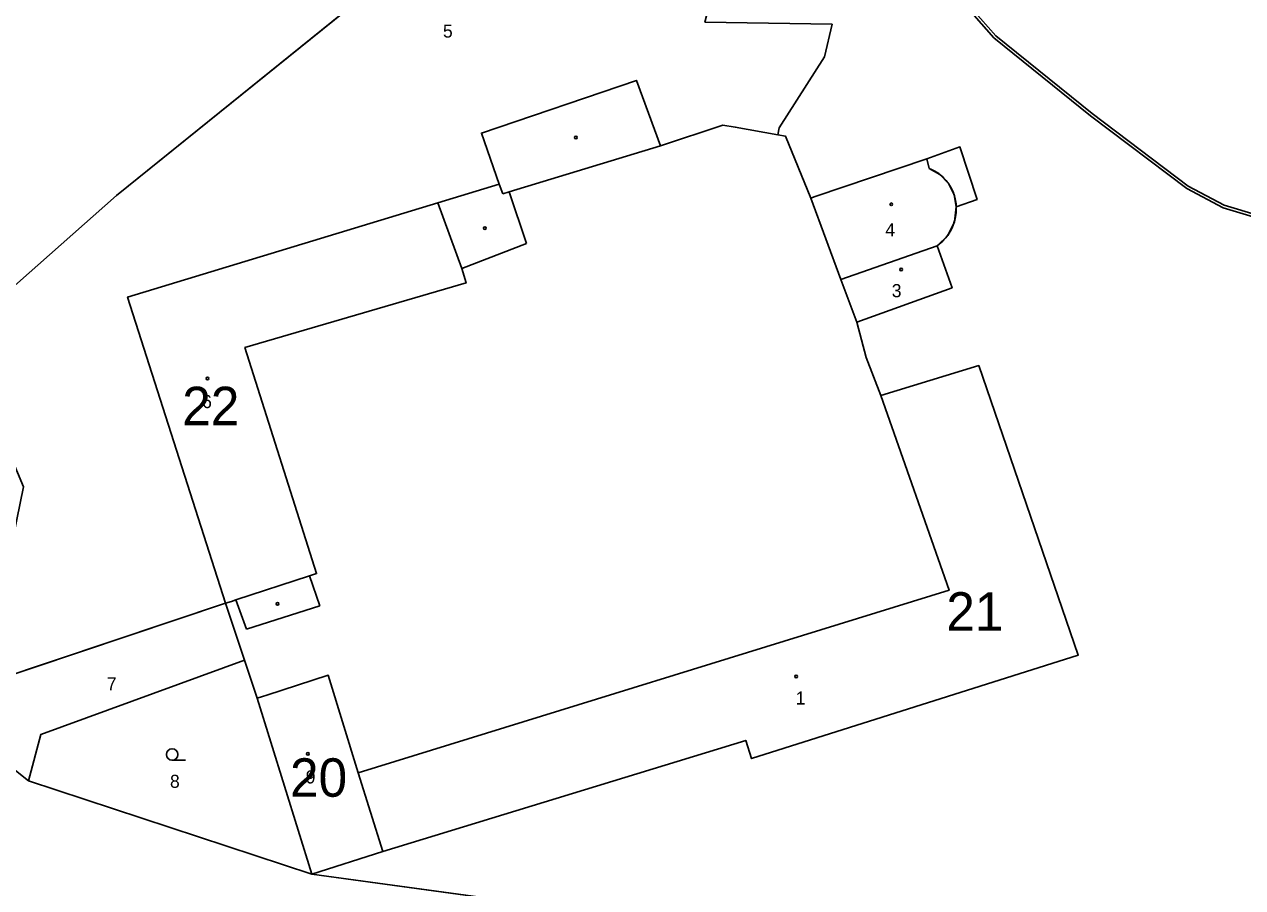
# Model space of a CAD drawing. Extents: x -689422 to -685210, y -987725 to -982160.
# Drawn here: x -686042.4 to -685883.9, y -987120.1 to -987007.8 of the extents above; entities that cross this region are included whole.
import ezdxf

# ---------------------------------------------------------------- set-up
doc = ezdxf.new("R2010")
doc.units = 0
for name, color, linetype in [('KN_Budovy', 7, 'Continuous'), ('KN_Budovy_cisla_domovni', 7, 'Continuous'), ('KN_Hranice_parcel', 7, 'Continuous'), ('KN_Hranice_parcel_vnitrni_kresba', 7, 'Continuous'), ('KN_Parcelni cisla', 7, 'Continuous'), ('KN_Polygon parcely', 7, 'Continuous'), ('KN_POZEMKY_ORNA PUDA', 7, 'Continuous'), ('KN_POZEMKY_OSTATNI PLOCHA', 7, 'Continuous'), ('KN_POZEMKY_TTP', 7, 'Continuous'), ('KN_POZEMKY_ZAHRADA', 7, 'Continuous'), ('KN_POZEMKY_ZASTAVENA PLOCHA', 7, 'Continuous'), ('KN_VYUZITI_16_ostatni plocha_silnice', 7, 'Continuous'), ('KN_VYUZITI_17_ostatni plocha_ostatni komunikace', 7, 'Continuous'), ('KN_VYUZITI_23_ostatni plocha_manipulacni plocha', 7, 'Continuous'), ('KN_Věcná břemena k části', 7, 'Continuous'), ('KN_Značky budov', 7, 'Continuous'), ('KN_Značky kultur', 7, 'Continuous')]:
    doc.layers.add(name, color=color, linetype=linetype)

msp = doc.modelspace()

# ---------------------------------------------------------------- linework, layer by layer
at = {"layer": 'KN_Budovy'}
for points in [[(-685939.49, -987030.22), (-685940.05, -987030.45), (-685936.15, -987041), (-685923.65, -987036.65), (-685922.26, -987035.27), (-685921.4, -987033.51), (-685921.15, -987031.56), (-685921.43, -987029.97), (-685922.16, -987028.54), (-685923.27, -987027.37), (-685924.67, -987026.57), (-685924.99, -987025.31)], [(-686028.95, -987043.29), (-686016.2, -987083.11), (-686015.44, -987082.86), (-686014.87, -987082.67), (-686005.31, -987079.54), (-686004.38, -987079.24), (-686013.69, -987049.87), (-685984.93, -987041.45), (-685985.48, -987039.58), (-685988.6, -987031.04)], [(-685934.1, -987046.54), (-685921.69, -987042.08), (-685923.65, -987036.65), (-685936.15, -987041)], [(-685998.97, -987105.14), (-685995.77, -987115.39), (-685948.53, -987100.93), (-685947.78, -987103.29), (-685905.27, -987089.86), (-685918.22, -987052.2), (-685930.96, -987056.09), (-685922.09, -987081.42)], [(-686012.08, -987095.43), (-686005, -987118.32), (-685995.77, -987115.39), (-685998.97, -987105.14), (-686002.86, -987092.46), (-686010.85, -987095.03), (-686011.42, -987095.22)]]:
    msp.add_lwpolyline(points, close=True, dxfattribs=at)
at = {"layer": 'KN_Hranice_parcel'}
for p, q in [((-685943.98, -986960.44), (-686030.41, -987030.08)), ((-686030.41, -987030.08), (-686044.81, -987042.84)), ((-685940.05, -987030.45), (-685936.15, -987041)), ((-685936.15, -987041), (-685923.65, -987036.65)), ((-685934.1, -987046.54), (-685936.15, -987041)), ((-686047.8, -987093.66), (-686016.2, -987083.11)), ((-686016.2, -987083.11), (-686013.73, -987090.49)), ((-686013.73, -987090.49), (-686012.08, -987095.43)), ((-686005, -987118.32), (-686012.08, -987095.43)), ((-686005, -987118.32), (-686041.83, -987106.17)), ((-685995.77, -987115.39), (-686005, -987118.32))]:
    msp.add_line(p, q, dxfattribs=at)
for points in [[(-685937.3, -987007.82), (-685938.29, -987012.04), (-685944.18, -987021.29), (-685944.36, -987022.19)], [(-685988.6, -987031.04), (-685980.6, -987028.61), (-685982.92, -987021.97), (-685962.77, -987015.13), (-685959.63, -987023.64), (-685951.53, -987020.94), (-685949.91, -987021.19), (-685944.36, -987022.19)], [(-685944.36, -987022.19), (-685943.35, -987022.38), (-685940.05, -987030.45)], [(-685924.99, -987025.31), (-685920.67, -987023.78), (-685918.44, -987030.6), (-685921.15, -987031.56)], [(-685940.05, -987030.45), (-685939.49, -987030.22), (-685924.99, -987025.31)], [(-686016.2, -987083.11), (-686028.95, -987043.29), (-685988.6, -987031.04)], [(-685988.6, -987031.04), (-685985.48, -987039.58), (-685984.93, -987041.45), (-686013.69, -987049.87), (-686004.38, -987079.24), (-686005.31, -987079.54), (-686014.87, -987082.67), (-686015.44, -987082.86), (-686016.2, -987083.11)], [(-685921.15, -987031.56), (-685921.17, -987032.33), (-685921.29, -987033.09), (-685921.51, -987033.83), (-685921.7, -987034.3), (-685922.07, -987034.98), (-685922.52, -987035.6), (-685923.05, -987036.16), (-685923.65, -987036.65)], [(-685923.65, -987036.65), (-685921.69, -987042.08), (-685934.1, -987046.54)], [(-685934.1, -987046.54), (-685932.88, -987051.14), (-685930.96, -987056.09), (-685918.22, -987052.2), (-685905.27, -987089.86), (-685947.78, -987103.29), (-685948.53, -987100.93), (-685995.77, -987115.39)], [(-686041.83, -987106.17), (-686052.84, -987097.52), (-686058.81, -987092.85), (-686061.49, -987085.48)], [(-686041.83, -987106.17), (-686040.25, -987100.18), (-686013.73, -987090.49)], [(-686012.08, -987095.43), (-686011.42, -987095.22), (-686010.85, -987095.03), (-686002.86, -987092.46), (-685998.97, -987105.14), (-685995.77, -987115.39)], [(-686005, -987118.32), (-685836.82, -987141.27), (-685828.14, -987142.95), (-685819.45, -987151.17)]]:
    msp.add_lwpolyline(points, dxfattribs=at)
at = {"layer": 'KN_Hranice_parcel_vnitrni_kresba'}
for p, q in [((-685979.31, -987029.61), (-685959.63, -987023.64)), ((-685924.99, -987025.31), (-685924.67, -987026.57)), ((-685980.6, -987028.61), (-685980.15, -987029.89)), ((-685980.15, -987029.89), (-685979.31, -987029.61)), ((-685979.31, -987029.61), (-685977.04, -987036.34)), ((-685985.48, -987039.58), (-685977.04, -987036.34)), ((-685930.96, -987056.09), (-685922.09, -987081.42)), ((-686005.31, -987079.54), (-686003.93, -987083.45)), ((-686014.87, -987082.67), (-686013.5, -987086.48)), ((-685998.97, -987105.14), (-685922.09, -987081.42)), ((-686013.5, -987086.48), (-686003.93, -987083.45))]:
    msp.add_line(p, q, dxfattribs=at)
msp.add_lwpolyline([(-685921.15, -987031.56), (-685921.16, -987031.35), (-685921.18, -987031.14), (-685921.2, -987030.94), (-685921.24, -987030.73), (-685921.28, -987030.53), (-685921.33, -987030.32), (-685921.38, -987030.12), (-685921.45, -987029.92), (-685921.52, -987029.73), (-685921.6, -987029.54), (-685921.69, -987029.34), (-685921.78, -987029.16), (-685921.88, -987028.97), (-685921.99, -987028.8), (-685922.1, -987028.62), (-685922.22, -987028.45), (-685922.35, -987028.29), (-685922.48, -987028.12), (-685922.62, -987027.97), (-685922.76, -987027.82), (-685922.91, -987027.67), (-685923.07, -987027.53), (-685923.23, -987027.4), (-685923.39, -987027.27), (-685923.57, -987027.15), (-685923.74, -987027.04), (-685923.92, -987026.93), (-685924.1, -987026.83), (-685924.29, -987026.74), (-685924.48, -987026.65), (-685924.67, -987026.57)], dxfattribs=at)
at = {"layer": 'KN_Polygon parcely'}
for points in [[(-686057.95, -987027.77), (-686044.81, -987042.84), (-686030.41, -987030.08), (-685943.98, -986960.44), (-685924.13, -986852.94), (-685913.21, -986806.14), (-685912.44, -986748.24), (-686007.7, -986854.28), (-685997.69, -986881.99), (-685975.19, -986944.25), (-685978.21, -986945.31), (-686044.53, -986968.62), (-686066.56, -986976.83), (-686064.65, -986989.12), (-686058.05, -987027.25)], [(-686016.2, -987083.11), (-686028.95, -987043.29), (-685988.6, -987031.04), (-685980.6, -987028.61), (-685982.92, -987021.97), (-685962.77, -987015.13), (-685959.63, -987023.64), (-685951.53, -987020.94), (-685949.91, -987021.19), (-685944.36, -987022.19), (-685944.18, -987021.29), (-685938.29, -987012.04), (-685937.3, -987007.82), (-685953.84, -987007.56), (-685941.2, -986958.77), (-685943.98, -986960.44), (-686030.41, -987030.08), (-686044.81, -987042.84), (-686051.22, -987045.66), (-686050.62, -987047.03), (-686049.49, -987051.75), (-686046.44, -987058.66), (-686042.51, -987067.97), (-686047.8, -987093.66)], [(-686013.73, -987090.49), (-686012.08, -987095.43), (-686011.42, -987095.22), (-686010.85, -987095.03), (-686002.86, -987092.46), (-685998.97, -987105.14), (-685995.77, -987115.39), (-685948.53, -987100.93), (-685947.78, -987103.29), (-685905.27, -987089.86), (-685918.22, -987052.2), (-685930.96, -987056.09), (-685932.88, -987051.14), (-685934.1, -987046.54), (-685936.15, -987041), (-685940.05, -987030.45), (-685943.35, -987022.38), (-685944.36, -987022.19), (-685949.91, -987021.19), (-685951.53, -987020.94), (-685959.63, -987023.64), (-685962.77, -987015.13), (-685982.92, -987021.97), (-685980.6, -987028.61), (-685988.6, -987031.04), (-685985.48, -987039.58), (-685984.93, -987041.45), (-686013.69, -987049.87), (-686004.38, -987079.24), (-686005.31, -987079.54), (-686014.87, -987082.67), (-686015.44, -987082.86), (-686016.2, -987083.11)], [(-685923.65, -987036.65), (-685923.05, -987036.16), (-685922.52, -987035.6), (-685922.07, -987034.98), (-685921.82, -987034.54), (-685921.51, -987033.83), (-685921.29, -987033.09), (-685921.17, -987032.33), (-685921.15, -987031.56), (-685918.44, -987030.6), (-685920.67, -987023.78), (-685924.99, -987025.31), (-685939.49, -987030.22), (-685940.05, -987030.45), (-685936.15, -987041)], [(-685988.6, -987031.04), (-686028.95, -987043.29), (-686016.2, -987083.11), (-686015.44, -987082.86), (-686014.87, -987082.67), (-686005.31, -987079.54), (-686004.38, -987079.24), (-686013.69, -987049.87), (-685984.93, -987041.45), (-685985.48, -987039.58)], [(-685934.1, -987046.54), (-685921.69, -987042.08), (-685923.65, -987036.65), (-685936.15, -987041)], [(-686013.73, -987090.49), (-686016.2, -987083.11), (-686047.8, -987093.66), (-686049.2, -987094.6), (-686052.96, -987093.52), (-686055.58, -987091.86), (-686059.81, -987087.86), (-686061.49, -987085.48), (-686058.81, -987092.85), (-686052.84, -987097.52), (-686041.83, -987106.17), (-686040.25, -987100.18)], [(-686005, -987118.32), (-686012.08, -987095.43), (-686013.73, -987090.49), (-686040.25, -987100.18), (-686041.83, -987106.17)], [(-685995.77, -987115.39), (-685998.97, -987105.14), (-686002.86, -987092.46), (-686010.85, -987095.03), (-686011.42, -987095.22), (-686012.08, -987095.43), (-686005, -987118.32)]]:
    msp.add_lwpolyline(points, close=True, dxfattribs=at)
for points in [[(-685836.82, -987141.27), (-686005, -987118.32), (-686041.83, -987106.17), (-686052.84, -987097.52), (-686058.81, -987092.85), (-686061.49, -987085.48), (-686064.52, -987080.49), (-686065.84, -987078.1), (-686071.7, -987067.5), (-686075.47, -987059.13), (-686075.94, -987058.09), (-686080.66, -987046.34), (-686084.5, -987036.79), (-686086.08, -987032.29), (-686090.96, -987018.42), (-686097.69, -986999.31)], [(-685937.3, -987007.82), (-685938.29, -987012.04), (-685944.18, -987021.29), (-685944.36, -987022.19), (-685943.35, -987022.38), (-685940.05, -987030.45), (-685939.49, -987030.22), (-685924.99, -987025.31), (-685920.67, -987023.78), (-685918.44, -987030.6), (-685921.15, -987031.56), (-685921.17, -987032.33), (-685921.29, -987033.09), (-685921.51, -987033.83), (-685921.7, -987034.3), (-685922.07, -987034.98), (-685922.52, -987035.6), (-685923.05, -987036.16), (-685923.65, -987036.65), (-685921.69, -987042.08), (-685934.1, -987046.54), (-685932.88, -987051.14), (-685930.96, -987056.09), (-685918.22, -987052.2), (-685905.27, -987089.86), (-685947.78, -987103.29), (-685948.53, -987100.93), (-685995.77, -987115.39), (-686005, -987118.32), (-685836.82, -987141.27)]]:
    msp.add_lwpolyline(points, dxfattribs=at)
at = {"layer": 'KN_POZEMKY_ORNA PUDA'}
for p, q in [((-685943.98, -986960.44), (-686030.41, -987030.08)), ((-686030.41, -987030.08), (-686044.81, -987042.84))]:
    msp.add_line(p, q, dxfattribs=at)
at = {"layer": 'KN_POZEMKY_OSTATNI PLOCHA'}
for p, q in [((-686030.41, -987030.08), (-685943.98, -986960.44)), ((-685937.3, -987007.82), (-685938.29, -987012.04)), ((-685938.29, -987012.04), (-685944.18, -987021.29)), ((-685962.77, -987015.13), (-685982.92, -987021.97)), ((-685959.63, -987023.64), (-685962.77, -987015.13)), ((-685951.53, -987020.94), (-685959.63, -987023.64)), ((-685949.91, -987021.19), (-685951.53, -987020.94)), ((-685982.92, -987021.97), (-685980.6, -987028.61)), ((-685944.36, -987022.19), (-685949.91, -987021.19)), ((-685944.18, -987021.29), (-685944.36, -987022.19)), ((-685980.6, -987028.61), (-685988.6, -987031.04)), ((-686044.81, -987042.84), (-686030.41, -987030.08)), ((-685988.6, -987031.04), (-686028.95, -987043.29)), ((-686028.95, -987043.29), (-686016.2, -987083.11)), ((-686016.2, -987083.11), (-686047.8, -987093.66)), ((-686047.8, -987093.66), (-686016.2, -987083.11)), ((-686016.2, -987083.11), (-686013.73, -987090.49)), ((-686013.73, -987090.49), (-686040.25, -987100.18)), ((-686041.83, -987106.17), (-686052.84, -987097.52)), ((-686052.84, -987097.52), (-686041.83, -987106.17)), ((-686040.25, -987100.18), (-686041.83, -987106.17)), ((-686041.83, -987106.17), (-686005, -987118.32)), ((-686005, -987118.32), (-685836.82, -987141.27))]:
    msp.add_line(p, q, dxfattribs=at)
at = {"layer": 'KN_POZEMKY_TTP'}
for p, q in [((-685938.29, -987012.04), (-685937.3, -987007.82)), ((-685944.18, -987021.29), (-685938.29, -987012.04)), ((-685944.36, -987022.19), (-685944.18, -987021.29)), ((-685943.35, -987022.38), (-685944.36, -987022.19)), ((-685940.05, -987030.45), (-685943.35, -987022.38)), ((-685920.67, -987023.78), (-685924.99, -987025.31)), ((-685918.44, -987030.6), (-685920.67, -987023.78)), ((-685924.99, -987025.31), (-685939.49, -987030.22)), ((-685939.49, -987030.22), (-685940.05, -987030.45)), ((-685921.19, -987032.54), (-685921.15, -987031.56)), ((-685921.15, -987031.56), (-685918.44, -987030.6)), ((-685921.15, -987031.56), (-685921.15, -987031.56)), ((-685921.76, -987034.42), (-685921.4, -987033.51)), ((-685921.4, -987033.51), (-685921.19, -987032.54)), ((-685922.9, -987036.02), (-685922.26, -987035.27)), ((-685922.26, -987035.27), (-685921.76, -987034.42)), ((-685923.65, -987036.65), (-685922.9, -987036.02)), ((-685921.69, -987042.08), (-685923.65, -987036.65)), ((-685934.1, -987046.54), (-685921.69, -987042.08)), ((-685932.88, -987051.14), (-685934.1, -987046.54)), ((-685930.96, -987056.09), (-685932.88, -987051.14)), ((-685918.22, -987052.2), (-685930.96, -987056.09)), ((-685905.27, -987089.86), (-685918.22, -987052.2)), ((-685947.78, -987103.29), (-685905.27, -987089.86)), ((-685995.77, -987115.39), (-685948.53, -987100.93)), ((-685948.53, -987100.93), (-685947.78, -987103.29)), ((-686005, -987118.32), (-685995.77, -987115.39)), ((-685836.82, -987141.27), (-686005, -987118.32))]:
    msp.add_line(p, q, dxfattribs=at)
at = {"layer": 'KN_POZEMKY_ZAHRADA'}
for p, q in [((-686040.25, -987100.18), (-686013.73, -987090.49)), ((-686013.73, -987090.49), (-686012.08, -987095.43)), ((-686012.08, -987095.43), (-686005, -987118.32)), ((-686041.83, -987106.17), (-686040.25, -987100.18)), ((-686005, -987118.32), (-686041.83, -987106.17))]:
    msp.add_line(p, q, dxfattribs=at)
at = {"layer": 'KN_POZEMKY_ZASTAVENA PLOCHA'}
for p, q in [((-685982.92, -987021.97), (-685962.77, -987015.13)), ((-685962.77, -987015.13), (-685959.63, -987023.64)), ((-685959.63, -987023.64), (-685951.53, -987020.94)), ((-685951.53, -987020.94), (-685949.91, -987021.19)), ((-685980.6, -987028.61), (-685982.92, -987021.97)), ((-685949.91, -987021.19), (-685944.36, -987022.19)), ((-685944.36, -987022.19), (-685943.35, -987022.38)), ((-685943.35, -987022.38), (-685940.05, -987030.45)), ((-685924.99, -987025.31), (-685920.67, -987023.78)), ((-685920.67, -987023.78), (-685918.44, -987030.6)), ((-685939.49, -987030.22), (-685924.99, -987025.31)), ((-685988.6, -987031.04), (-685980.6, -987028.61)), ((-685940.05, -987030.45), (-685939.49, -987030.22)), ((-685940.05, -987030.45), (-685936.15, -987041)), ((-685936.15, -987041), (-685940.05, -987030.45)), ((-686028.95, -987043.29), (-685988.6, -987031.04)), ((-685985.48, -987039.58), (-685988.6, -987031.04)), ((-685988.6, -987031.04), (-685985.48, -987039.58)), ((-685921.15, -987031.56), (-685921.19, -987032.54)), ((-685918.44, -987030.6), (-685921.15, -987031.56)), ((-685921.4, -987033.51), (-685921.76, -987034.42)), ((-685921.19, -987032.54), (-685921.4, -987033.51)), ((-685922.26, -987035.27), (-685922.9, -987036.02)), ((-685921.76, -987034.42), (-685922.26, -987035.27)), ((-685923.65, -987036.65), (-685936.15, -987041)), ((-685936.15, -987041), (-685923.65, -987036.65)), ((-685922.9, -987036.02), (-685923.65, -987036.65)), ((-685923.65, -987036.65), (-685923.65, -987036.65)), ((-685923.65, -987036.65), (-685921.69, -987042.08)), ((-685984.93, -987041.45), (-685985.48, -987039.58)), ((-685985.48, -987039.58), (-685984.93, -987041.45)), ((-686013.69, -987049.87), (-685984.93, -987041.45)), ((-685984.93, -987041.45), (-686013.69, -987049.87)), ((-685936.15, -987041), (-685934.1, -987046.54)), ((-685934.1, -987046.54), (-685936.15, -987041)), ((-685921.69, -987042.08), (-685934.1, -987046.54)), ((-686016.2, -987083.11), (-686028.95, -987043.29)), ((-685934.1, -987046.54), (-685932.88, -987051.14)), ((-686004.38, -987079.24), (-686013.69, -987049.87)), ((-686013.69, -987049.87), (-686004.38, -987079.24)), ((-685932.88, -987051.14), (-685930.96, -987056.09)), ((-685930.96, -987056.09), (-685918.22, -987052.2)), ((-685918.22, -987052.2), (-685905.27, -987089.86)), ((-686014.87, -987082.67), (-686005.31, -987079.54)), ((-686005.31, -987079.54), (-686014.87, -987082.67)), ((-686005.31, -987079.54), (-686004.38, -987079.24)), ((-686004.38, -987079.24), (-686005.31, -987079.54)), ((-686016.2, -987083.11), (-686015.44, -987082.86)), ((-686015.44, -987082.86), (-686016.2, -987083.11)), ((-686015.44, -987082.86), (-686014.87, -987082.67)), ((-686014.87, -987082.67), (-686015.44, -987082.86)), ((-686013.73, -987090.49), (-686016.2, -987083.11)), ((-686012.08, -987095.43), (-686013.73, -987090.49)), ((-685905.27, -987089.86), (-685947.78, -987103.29)), ((-686010.85, -987095.03), (-686002.86, -987092.46)), ((-686002.86, -987092.46), (-686010.85, -987095.03)), ((-686002.86, -987092.46), (-685998.97, -987105.14)), ((-685998.97, -987105.14), (-686002.86, -987092.46)), ((-686012.08, -987095.43), (-686011.42, -987095.22)), ((-686011.42, -987095.22), (-686012.08, -987095.43)), ((-686005, -987118.32), (-686012.08, -987095.43)), ((-686011.42, -987095.22), (-686010.85, -987095.03)), ((-686010.85, -987095.03), (-686011.42, -987095.22)), ((-685948.53, -987100.93), (-685995.77, -987115.39)), ((-685947.78, -987103.29), (-685948.53, -987100.93)), ((-685998.97, -987105.14), (-685995.77, -987115.39)), ((-685995.77, -987115.39), (-685998.97, -987105.14)), ((-685995.77, -987115.39), (-686005, -987118.32))]:
    msp.add_line(p, q, dxfattribs=at)
at = {"layer": 'KN_VYUZITI_16_ostatni plocha_silnice'}
for p, q in [((-686052.84, -987097.52), (-686041.83, -987106.17)), ((-686041.83, -987106.17), (-686005, -987118.32)), ((-686005, -987118.32), (-685836.82, -987141.27))]:
    msp.add_line(p, q, dxfattribs=at)
at = {"layer": 'KN_VYUZITI_17_ostatni plocha_ostatni komunikace'}
for p, q in [((-686047.8, -987093.66), (-686016.2, -987083.11)), ((-686016.2, -987083.11), (-686013.73, -987090.49)), ((-686013.73, -987090.49), (-686040.25, -987100.18)), ((-686041.83, -987106.17), (-686052.84, -987097.52)), ((-686040.25, -987100.18), (-686041.83, -987106.17))]:
    msp.add_line(p, q, dxfattribs=at)
at = {"layer": 'KN_VYUZITI_23_ostatni plocha_manipulacni plocha'}
for p, q in [((-686030.41, -987030.08), (-685943.98, -986960.44)), ((-685937.3, -987007.82), (-685938.29, -987012.04)), ((-685938.29, -987012.04), (-685944.18, -987021.29)), ((-685962.77, -987015.13), (-685982.92, -987021.97)), ((-685959.63, -987023.64), (-685962.77, -987015.13)), ((-685951.53, -987020.94), (-685959.63, -987023.64)), ((-685949.91, -987021.19), (-685951.53, -987020.94)), ((-685982.92, -987021.97), (-685980.6, -987028.61)), ((-685944.36, -987022.19), (-685949.91, -987021.19)), ((-685944.18, -987021.29), (-685944.36, -987022.19)), ((-685980.6, -987028.61), (-685988.6, -987031.04)), ((-686044.81, -987042.84), (-686030.41, -987030.08)), ((-685988.6, -987031.04), (-686028.95, -987043.29)), ((-686028.95, -987043.29), (-686016.2, -987083.11)), ((-686016.2, -987083.11), (-686047.8, -987093.66))]:
    msp.add_line(p, q, dxfattribs=at)
at = {"layer": 'KN_Věcná břemena k části'}
msp.add_lwpolyline([(-685934.6, -986984.59), (-685934.66, -986985.17), (-685929.79, -986993.25), (-685925.24, -986999.35), (-685916.25, -987009.6), (-685903.69, -987019.71), (-685891.14, -987029.18), (-685886.44, -987031.68), (-685877, -987034.5), (-685854.55, -987038.35), (-685854.26, -987038.04), (-685854.44, -987038.01), (-685876.92, -987034.16), (-685886.3, -987031.36), (-685890.96, -987028.88), (-685903.47, -987019.43), (-685916.01, -987009.34), (-685924.96, -986999.13), (-685929.49, -986993.05)], close=True, dxfattribs=at)
at = {"layer": 'KN_Značky budov'}
for centre in [(-685970.63, -987022.55), (-685929.6, -987031.23), (-685982.48, -987034.33), (-685928.32, -987039.72), (-686018.57, -987053.87), (-686009.44, -987083.19), (-685941.98, -987092.61), (-686005.5, -987102.68)]:
    msp.add_circle(centre, 0.175, dxfattribs=at)
at = {"layer": 'KN_Značky kultur'}
msp.add_line((-686023.16, -987103.52), (-686021.41, -987103.52), dxfattribs=at)
msp.add_circle((-686023.16, -987102.77), 0.75, dxfattribs=at)

# ---------------------------------------------------------------- texts
at = {"layer": 'KN_Budovy_cisla_domovni'}
for s, p in [('22', (-686021.85, -987059.95)), ('21', (-685922.45, -987086.67)), ('20', (-686007.83, -987108.26))]:
    msp.add_text(s, height=5, dxfattribs=at).set_placement(p)
at = {"layer": 'KN_Parcelni cisla'}
for s, p in [('5', (-685987.93, -987009.56)), ('4', (-685930.38, -987035.39)), ('3', (-685929.54, -987043.31)), ('6', (-686019.26, -987057.73)), ('7', (-686031.65, -987094.42)), ('1', (-685942.03, -987096.27)), ('9', (-686005.78, -987106.53)), ('8', (-686023.44, -987107.1))]:
    msp.add_text(s, height=1.7, dxfattribs=at).set_placement(p)

doc.saveas('drawing.dxf')
